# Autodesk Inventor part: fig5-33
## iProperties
Created: 2005-12
Part Number: fig5-33
Document SubType Name: Modeling
Designer: CADCIM
Density: 1 g/cm^3
Author: CADCIM
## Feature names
1. Extrusion1
